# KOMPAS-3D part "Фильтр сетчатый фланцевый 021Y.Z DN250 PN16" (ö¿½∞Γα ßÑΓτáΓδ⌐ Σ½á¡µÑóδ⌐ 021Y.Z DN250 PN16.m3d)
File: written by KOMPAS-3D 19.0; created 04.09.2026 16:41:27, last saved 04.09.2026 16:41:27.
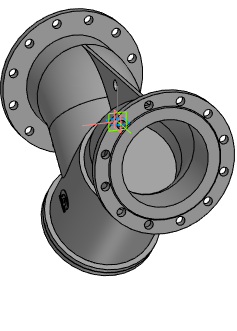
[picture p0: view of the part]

Document properties: Автор: Энергия; Полное имя файла: Z:\3.Личные\sachek\Dendor\_3D для проектировщиков\8.1 Фильтр сетчатый 021Y.Z\021Y.Z_STP\Фильтр сетчатый фланцевый 021Y.Z DN250 PN16.m3d

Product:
- Part/product: Фильтр сетчатый фланцевый 021Y.Z DN250 PN16

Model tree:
1. Операция без истории:1  (labels: Фильтр сетчатый фланцевый 021Y.Z DN250 PN16)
